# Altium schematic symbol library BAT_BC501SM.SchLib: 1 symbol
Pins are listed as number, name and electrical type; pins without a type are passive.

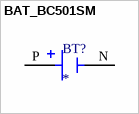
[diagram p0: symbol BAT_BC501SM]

## BAT_BC501SM
designator BT?
BATTERY HOLDER COIN 12MM SMD; MF: MPD; MP: BC501SM
footprint BAT_BC501SM
pins: N NEG, P POS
